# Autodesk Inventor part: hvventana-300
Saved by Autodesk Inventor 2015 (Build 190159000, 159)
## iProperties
Created: 2020-08
Part Number: hvventana-300
Checked By: TraceParts S.A.
Material: Generic
Catalog Web Link: www.traceparts.com
Document SubType Name: Modeling
Designer: TraceParts
Density: 1 g/cm^3
Appearance: Default
Company: TraceParts S.A.
Author: TraceParts
REFERENCE: HVVENTANA-300
SUPPLIER: Soler & Palau
DESIGN: HVVENTANA-300
TraceParts.PartNumber: 10-04022019-080750
TraceParts.PartTitle: HV-STYLVENT
TraceParts.InstanceId: 10-04022019-080750DJ0EHDYW5B84H79S7IK93F69C
TraceParts.PartVersion: 1.0.1
TraceParts.PartStatus: Published
TRACEPARTS: TRACEPARTS
TraceParts.PartLanguage: en
TraceParts.ClassPath: SOLER_PALAU:10-04022019-080750
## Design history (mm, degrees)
feature "hvventana-300"
body "Solid1"
